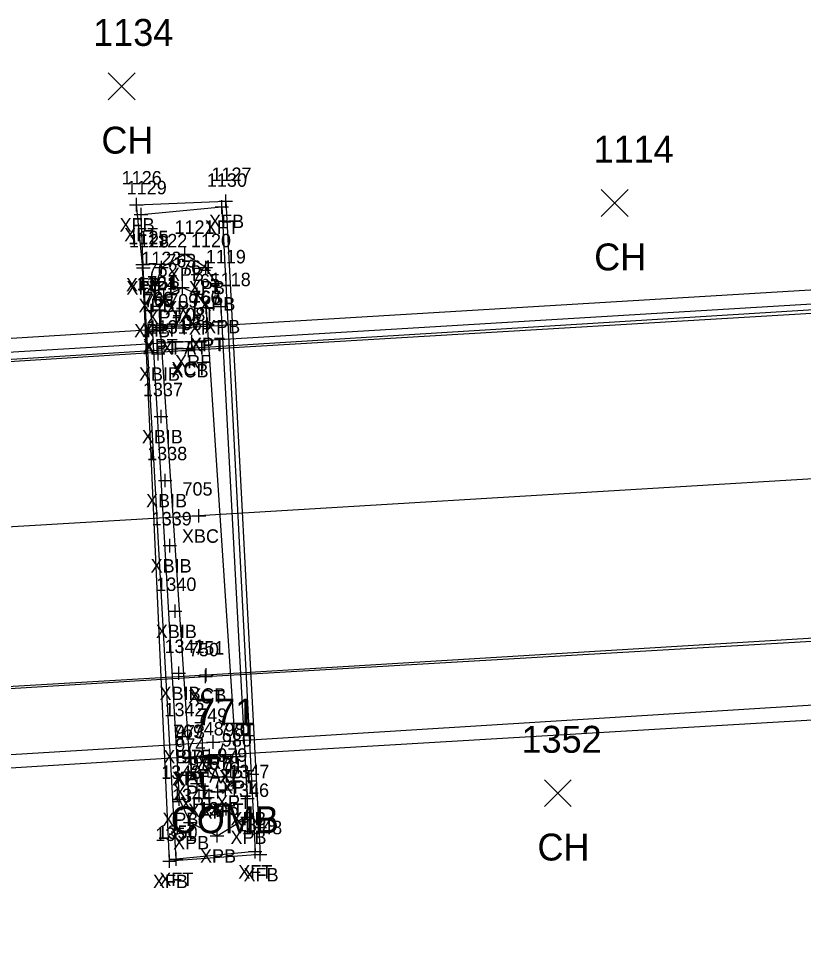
# Model space of a CAD drawing. Extents: x 1715662 to 1717487, y 887396 to 890004.
# Drawn here: x 1717104.2 to 1717162.5, y 888212.7 to 888281.6 of the extents above; entities that cross this region are included whole.
import ezdxf

# ---------------------------------------------------------------- set-up
doc = ezdxf.new("R2010")
doc.units = 0
for name, color, linetype in [('B_A', 7, 'Continuous'), ('B_I', 7, 'Continuous'), ('B_TIC', 7, 'Continuous'), ('BDC', 7, 'Continuous'), ('BELB', 7, 'Continuous'), ('BF', 7, 'Continuous'), ('BFT', 7, 'Continuous'), ('BR', 7, 'Continuous'), ('BSUBM', 7, 'Continuous'), ('L_A', 7, 'Continuous'), ('L_I', 7, 'Continuous'), ('L_TIC', 7, 'Continuous'), ('U_A', 7, 'Continuous'), ('U_I', 7, 'Continuous'), ('UP', 7, 'Continuous')]:
    doc.layers.add(name, color=color, linetype=linetype)

msp = doc.modelspace()

# ---------------------------------------------------------------- linework, layer by layer
at = {"layer": 'B_TIC'}
for p, q in [((1717112.953, 888267.77), (1717113.029, 888267.77)), ((1717119.298, 888267.599), (1717119.374, 888267.599)), ((1717119.593, 888268.03), (1717119.669, 888268.03)), ((1717113.302, 888267.041), (1717113.378, 888267.041)), ((1717116.563, 888264.1), (1717116.639, 888264.1)), ((1717113.421, 888263.334), (1717113.497, 888263.334)), ((1717113.469, 888263.093), (1717113.544, 888263.093)), ((1717114.823, 888263.1), (1717114.899, 888263.1)), ((1717118.113, 888263.11), (1717118.189, 888263.11)), ((1717114.383, 888261.78), (1717114.459, 888261.78)), ((1717116.378, 888261.612), (1717116.453, 888261.612)), ((1717118.893, 888261.91), (1717118.969, 888261.91)), ((1717114.993, 888260.931), (1717115.068, 888260.931)), ((1717117.481, 888261.13), (1717117.557, 888261.13)), ((1717118.138, 888260.129), (1717118.214, 888260.129)), ((1717119.253, 888260.22), (1717119.329, 888260.22)), ((1717114.043, 888259.92), (1717114.119, 888259.92)), ((1717114.671, 888259.963), (1717114.747, 888259.963)), ((1717114.707, 888258.8), (1717114.782, 888258.8)), ((1717114.723, 888258.654), (1717114.798, 888258.654)), ((1717116.542, 888258.636), (1717116.617, 888258.636)), ((1717118.201, 888258.895), (1717118.276, 888258.895)), ((1717118.23, 888258.881), (1717118.306, 888258.881)), ((1717117.065, 888257.612), (1717117.141, 888257.612)), ((1717114.573, 888256.694), (1717114.649, 888256.694)), ((1717116.83, 888256.946), (1717116.906, 888256.946)), ((1717116.833, 888257.088), (1717116.908, 888257.088)), ((1717114.787, 888252.047), (1717114.863, 888252.047)), ((1717115.1, 888247.294), (1717115.176, 888247.294)), ((1717117.602, 888244.664), (1717117.678, 888244.664)), ((1717115.442, 888242.454), (1717115.517, 888242.454)), ((1717115.827, 888237.586), (1717115.903, 888237.586)), ((1717116.104, 888232.979), (1717116.18, 888232.979)), ((1717118.077, 888232.734), (1717118.153, 888232.734)), ((1717118.151, 888232.862), (1717118.226, 888232.862)), ((1717116.387, 888228.279), (1717116.463, 888228.279)), ((1717118.657, 888227.867), (1717118.733, 888227.867)), ((1717116.881, 888226.664), (1717116.956, 888226.664)), ((1717117.001, 888226.634), (1717117.076, 888226.634)), ((1717118.391, 888226.857), (1717118.467, 888226.857)), ((1717120.369, 888226.798), (1717120.445, 888226.798)), ((1717120.401, 888226.793), (1717120.476, 888226.793)), ((1717117.029, 888225.645), (1717117.105, 888225.645)), ((1717120.53, 888226.027), (1717120.606, 888226.027)), ((1717120.147, 888224.902), (1717120.223, 888224.902)), ((1717117.467, 888224.792), (1717117.542, 888224.792)), ((1717118.075, 888224.298), (1717118.15, 888224.298)), ((1717118.994, 888224.182), (1717119.069, 888224.182)), ((1717119.585, 888224.316), (1717119.66, 888224.316)), ((1717116.145, 888223.627), (1717116.221, 888223.627)), ((1717121.205, 888223.683), (1717121.28, 888223.683)), ((1717121.207, 888222.295), (1717121.282, 888222.295)), ((1717116.95, 888221.897), (1717117.025, 888221.897)), ((1717118.945, 888220.911), (1717119.02, 888220.911)), ((1717121.779, 888219.728), (1717121.854, 888219.728)), ((1717122.153, 888219.52), (1717122.229, 888219.52)), ((1717115.423, 888219.02), (1717115.499, 888219.02)), ((1717115.913, 888219.18), (1717115.989, 888219.18))]:
    msp.add_line(p, q, dxfattribs=at)
for points in [[(1717112.95, 888267.27), (1717112.95, 888268.27)], [(1717119.59, 888267.53), (1717119.59, 888268.53)], [(1717112.45, 888267.77), (1717113.45, 888267.77)], [(1717118.795, 888267.599), (1717119.795, 888267.599)], [(1717119.09, 888268.03), (1717120.09, 888268.03)], [(1717119.295, 888267.099), (1717119.295, 888268.099)], [(1717112.799, 888267.041), (1717113.799, 888267.041)], [(1717113.299, 888266.541), (1717113.299, 888267.541)], [(1717116.56, 888263.6), (1717116.56, 888264.6)], [(1717113.418, 888262.834), (1717113.418, 888263.834)], [(1717113.465, 888262.593), (1717113.465, 888263.593)], [(1717114.82, 888262.6), (1717114.82, 888263.6)], [(1717116.06, 888264.1), (1717117.06, 888264.1)], [(1717118.11, 888262.61), (1717118.11, 888263.61)], [(1717112.918, 888263.334), (1717113.918, 888263.334)], [(1717112.965, 888263.093), (1717113.965, 888263.093)], [(1717114.32, 888263.1), (1717115.32, 888263.1)], [(1717117.61, 888263.11), (1717118.61, 888263.11)], [(1717114.38, 888261.28), (1717114.38, 888262.28)], [(1717116.374, 888261.112), (1717116.374, 888262.112)], [(1717118.89, 888261.41), (1717118.89, 888262.41)], [(1717113.88, 888261.78), (1717114.88, 888261.78)], [(1717114.989, 888260.431), (1717114.989, 888261.431)], [(1717115.874, 888261.612), (1717116.874, 888261.612)], [(1717117.478, 888260.63), (1717117.478, 888261.63)], [(1717118.39, 888261.91), (1717119.39, 888261.91)], [(1717114.489, 888260.931), (1717115.489, 888260.931)], [(1717116.978, 888261.13), (1717117.978, 888261.13)], [(1717119.25, 888259.72), (1717119.25, 888260.72)], [(1717114.04, 888259.42), (1717114.04, 888260.42)], [(1717114.668, 888259.463), (1717114.668, 888260.463)], [(1717117.635, 888260.129), (1717118.635, 888260.129)], [(1717118.135, 888259.629), (1717118.135, 888260.629)], [(1717118.75, 888260.22), (1717119.75, 888260.22)], [(1717113.54, 888259.92), (1717114.54, 888259.92)], [(1717114.168, 888259.963), (1717115.168, 888259.963)], [(1717114.703, 888258.3), (1717114.703, 888259.3)], [(1717118.197, 888258.395), (1717118.197, 888259.395)], [(1717118.227, 888258.381), (1717118.227, 888259.381)], [(1717114.203, 888258.8), (1717115.203, 888258.8)], [(1717114.219, 888258.654), (1717115.219, 888258.654)], [(1717114.719, 888258.154), (1717114.719, 888259.154)], [(1717116.038, 888258.636), (1717117.038, 888258.636)], [(1717116.538, 888258.136), (1717116.538, 888259.136)], [(1717117.697, 888258.895), (1717118.697, 888258.895)], [(1717117.727, 888258.881), (1717118.727, 888258.881)], [(1717117.062, 888257.112), (1717117.062, 888258.112)], [(1717116.562, 888257.612), (1717117.562, 888257.612)], [(1717116.827, 888256.446), (1717116.827, 888257.446)], [(1717116.829, 888256.588), (1717116.829, 888257.588)], [(1717114.07, 888256.694), (1717115.07, 888256.694)], [(1717114.57, 888256.194), (1717114.57, 888257.194)], [(1717116.327, 888256.946), (1717117.327, 888256.946)], [(1717116.329, 888257.088), (1717117.329, 888257.088)], [(1717114.784, 888251.547), (1717114.784, 888252.547)], [(1717114.284, 888252.047), (1717115.284, 888252.047)], [(1717115.097, 888246.794), (1717115.097, 888247.794)], [(1717114.597, 888247.294), (1717115.597, 888247.294)], [(1717117.599, 888244.164), (1717117.599, 888245.164)], [(1717117.099, 888244.664), (1717118.099, 888244.664)], [(1717115.438, 888241.954), (1717115.438, 888242.954)], [(1717114.938, 888242.454), (1717115.938, 888242.454)], [(1717115.824, 888237.086), (1717115.824, 888238.086)], [(1717115.324, 888237.586), (1717116.324, 888237.586)], [(1717116.101, 888232.479), (1717116.101, 888233.479)], [(1717118.074, 888232.234), (1717118.074, 888233.234)], [(1717118.147, 888232.362), (1717118.147, 888233.362)], [(1717115.601, 888232.979), (1717116.601, 888232.979)], [(1717117.574, 888232.734), (1717118.574, 888232.734)], [(1717117.647, 888232.862), (1717118.647, 888232.862)], [(1717116.384, 888227.779), (1717116.384, 888228.779)], [(1717118.654, 888227.367), (1717118.654, 888228.367)], [(1717115.884, 888228.279), (1717116.884, 888228.279)], [(1717118.154, 888227.867), (1717119.154, 888227.867)], [(1717116.877, 888226.164), (1717116.877, 888227.164)], [(1717116.997, 888226.134), (1717116.997, 888227.134)], [(1717118.388, 888226.357), (1717118.388, 888227.357)], [(1717120.366, 888226.298), (1717120.366, 888227.298)], [(1717120.397, 888226.293), (1717120.397, 888227.293)], [(1717116.377, 888226.664), (1717117.377, 888226.664)], [(1717116.497, 888226.634), (1717117.497, 888226.634)], [(1717117.888, 888226.857), (1717118.888, 888226.857)], [(1717119.866, 888226.798), (1717120.866, 888226.798)], [(1717119.897, 888226.793), (1717120.897, 888226.793)], [(1717120.527, 888225.527), (1717120.527, 888226.527)], [(1717116.526, 888225.645), (1717117.526, 888225.645)], [(1717117.026, 888225.145), (1717117.026, 888226.145)], [(1717120.027, 888226.027), (1717121.027, 888226.027)], [(1717117.463, 888224.292), (1717117.463, 888225.292)], [(1717119.644, 888224.902), (1717120.644, 888224.902)], [(1717120.144, 888224.402), (1717120.144, 888225.402)], [(1717116.963, 888224.792), (1717117.963, 888224.792)], [(1717117.571, 888224.298), (1717118.571, 888224.298)], [(1717118.071, 888223.798), (1717118.071, 888224.798)], [(1717118.49, 888224.182), (1717119.49, 888224.182)], [(1717118.99, 888223.682), (1717118.99, 888224.682)], [(1717119.081, 888224.316), (1717120.081, 888224.316)], [(1717119.581, 888223.816), (1717119.581, 888224.816)], [(1717121.201, 888223.183), (1717121.201, 888224.183)], [(1717115.642, 888223.627), (1717116.642, 888223.627)], [(1717116.142, 888223.127), (1717116.142, 888224.127)], [(1717120.701, 888223.683), (1717121.701, 888223.683)], [(1717121.203, 888221.795), (1717121.203, 888222.795)], [(1717116.946, 888221.397), (1717116.946, 888222.397)], [(1717120.703, 888222.295), (1717121.703, 888222.295)], [(1717116.446, 888221.897), (1717117.446, 888221.897)], [(1717118.941, 888220.411), (1717118.941, 888221.411)], [(1717118.441, 888220.911), (1717119.441, 888220.911)], [(1717121.776, 888219.228), (1717121.776, 888220.228)], [(1717115.42, 888218.52), (1717115.42, 888219.52)], [(1717115.91, 888218.68), (1717115.91, 888219.68)], [(1717121.276, 888219.728), (1717122.276, 888219.728)], [(1717121.65, 888219.52), (1717122.65, 888219.52)], [(1717122.15, 888219.02), (1717122.15, 888220.02)], [(1717114.92, 888219.02), (1717115.92, 888219.02)], [(1717115.41, 888219.18), (1717116.41, 888219.18)]]:
    msp.add_lwpolyline(points, dxfattribs=at)
at = {"layer": 'BDC'}
for points in [[(1717176.589, 888262.234), (1717176.877, 888260.812), (1717116.829, 888257.088), (1717056.7, 888253.344), (1716997.03, 888249.858), (1716936.998, 888246.313), (1716877.496, 888242.928), (1716877.301, 888244.49)], [(1717176.976, 888262.024), (1717176.866, 888260.514), (1717116.827, 888256.946), (1717056.83, 888253.148), (1716997.002, 888249.663), (1716937.062, 888246.095), (1716877.423, 888242.56)], [(1716878.985, 888212.69), (1716878.754, 888218.609), (1716938.217, 888221.984), (1716998.215, 888225.489), (1717058.321, 888229.074), (1717118.074, 888232.734), (1717177.978, 888236.214), (1717178.104, 888235.65), (1717178.633, 888230.445)], [(1716878.76, 888218.785), (1716938.254, 888222.245), (1716997.847, 888225.861), (1717058.278, 888229.335), (1717118.147, 888232.862), (1717177.913, 888236.497)]]:
    msp.add_lwpolyline(points, dxfattribs=at)
at = {"layer": 'BELB'}
msp.add_lwpolyline([(1717176.82, 888248.242), (1717117.599, 888244.664), (1717057.58, 888241.128), (1716997.658, 888237.527), (1716937.868, 888233.85), (1716878.264, 888230.514)], dxfattribs=at)
at = {"layer": 'BF'}
for points in [[(1717176.589, 888262.234), (1717116.538, 888258.636), (1717056.61, 888254.944), (1716996.925, 888251.433), (1716937.102, 888247.945), (1716877.301, 888244.49)], [(1716878.985, 888212.69), (1716938.928, 888216.097), (1716998.537, 888219.726), (1717058.79, 888223.18), (1717118.388, 888226.857), (1717178.633, 888230.445)]]:
    msp.add_lwpolyline(points, dxfattribs=at)
at = {"layer": 'BFT'}
for points in [[(1717113.418, 888263.334), (1717112.95, 888267.77), (1717119.59, 888268.03), (1717122.15, 888219.52), (1717115.42, 888219.02)], [(1717113.465, 888263.093), (1717113.299, 888267.041), (1717119.295, 888267.599), (1717121.776, 888219.728), (1717115.91, 888219.18)], [(1717115.42, 888219.02), (1717113.418, 888263.334)], [(1717115.91, 888219.18), (1717113.465, 888263.093)]]:
    msp.add_lwpolyline(points, dxfattribs=at)
at = {"layer": 'BR'}
for points in [[(1717175.997, 888261.982), (1717175.88, 888261.141), (1717117.062, 888257.612), (1717056.557, 888253.997), (1716997.021, 888250.409), (1716936.966, 888246.784), (1716878.141, 888243.386), (1716877.962, 888244.411)], [(1716879.623, 888212.902), (1716879.679, 888213.775), (1716938.703, 888217.127), (1716998.522, 888220.762), (1717058.504, 888224.208), (1717118.654, 888227.867), (1717177.581, 888231.531), (1717177.859, 888230.636)]]:
    msp.add_lwpolyline(points, dxfattribs=at)
at = {"layer": 'BSUBM'}
for points in [[(1717119.25, 888260.22), (1717118.89, 888261.91), (1717118.11, 888263.11), (1717116.56, 888264.1), (1717114.82, 888263.1), (1717114.38, 888261.78), (1717114.04, 888259.92), (1717116.142, 888223.627), (1717116.946, 888221.897), (1717118.941, 888220.911), (1717121.203, 888222.295), (1717121.201, 888223.683)], [(1717114.703, 888258.8), (1717114.668, 888259.963), (1717114.989, 888260.931), (1717116.374, 888261.612), (1717117.478, 888261.13), (1717118.135, 888260.129), (1717118.197, 888258.895)], [(1717121.201, 888223.683), (1717119.25, 888260.22)], [(1717118.197, 888258.895), (1717114.703, 888258.8)], [(1717118.227, 888258.881), (1717114.719, 888258.654), (1717116.877, 888226.664), (1717120.366, 888226.798)], [(1717120.366, 888226.798), (1717118.227, 888258.881)], [(1717116.997, 888226.634), (1717117.026, 888225.645), (1717117.463, 888224.792), (1717118.071, 888224.298), (1717118.99, 888224.182), (1717119.581, 888224.316), (1717120.144, 888224.902), (1717120.527, 888226.027), (1717120.397, 888226.793)], [(1717120.397, 888226.793), (1717116.997, 888226.634)]]:
    msp.add_lwpolyline(points, dxfattribs=at)
at = {"layer": 'L_TIC'}
for points in [[(1717110.868, 888275.562), (1717112.868, 888277.562)], [(1717112.868, 888275.562), (1717110.868, 888277.562)], [(1717147.467, 888266.891), (1717149.467, 888268.891)], [(1717149.467, 888266.891), (1717147.467, 888268.891)], [(1717143.251, 888223.071), (1717145.251, 888225.071)], [(1717145.251, 888223.071), (1717143.251, 888225.071)]]:
    msp.add_lwpolyline(points, dxfattribs=at)
at = {"layer": 'UP'}
for p, q in [((1717119.37, 888227.765), (1717119.12, 888226.932)), ((1717118.286, 888225.265), (1717118.286, 888226.932)), ((1717118.286, 888226.932), (1717119.953, 888226.932)), ((1717119.953, 888226.932), (1717119.953, 888225.265)), ((1717119.12, 888226.099), (1717119.12, 888226.099)), ((1717119.953, 888225.265), (1717118.286, 888225.265)), ((1717118.87, 888224.432), (1717119.12, 888225.265))]:
    msp.add_line(p, q, dxfattribs=at)
msp.add_circle((1717119.12, 888226.099), 0.833, dxfattribs=at)

# ---------------------------------------------------------------- texts
at = {"layer": 'B_A'}
for s, p in [('XFB', (1717118.35, 888266.03)), ('XFB', (1717111.71, 888265.77)), ('XFT', (1717118.039, 888265.599)), ('XFT', (1717112.043, 888265.041)), ('XPB', (1717115.296, 888262.1)), ('XFB', (1717112.178, 888261.334)), ('XFT', (1717112.21, 888261.093)), ('XPB', (1717113.556, 888261.1)), ('XPB', (1717116.846, 888261.11)), ('XPB', (1717113.116, 888259.78)), ('XPB', (1717117.626, 888259.91)), ('XPT', (1717115.095, 888259.612)), ('XPT', (1717116.198, 888259.13)), ('XPT', (1717113.71, 888258.931)), ('XPB', (1717112.776, 888257.92)), ('XPT', (1717113.388, 888257.963)), ('XPT', (1717116.855, 888258.129)), ('XPB', (1717117.986, 888258.22)), ('XPT', (1717113.424, 888256.8)), ('XPT', (1717113.44, 888256.654)), ('XFAT', (1717114.794, 888256.636)), ('XPT', (1717116.918, 888256.895)), ('XPT', (1717116.947, 888256.881)), ('XRF', (1717115.822, 888255.612)), ('XCT', (1717115.55, 888255.088)), ('XCB', (1717115.563, 888254.946)), ('XBIB', (1717113.141, 888254.694)), ('XBIB', (1717113.355, 888250.047)), ('XBIB', (1717113.668, 888245.294)), ('XBC', (1717116.335, 888242.664)), ('XBIB', (1717114.009, 888240.454)), ('XBIB', (1717114.395, 888235.586)), ('XBIB', (1717114.671, 888230.979)), ('XCT', (1717116.794, 888230.734)), ('XCB', (1717116.884, 888230.862)), ('XBIB', (1717114.955, 888226.279)), ('XRF', (1717117.414, 888225.867)), ('XPT', (1717115.598, 888224.664)), ('XPT', (1717115.718, 888224.634)), ('XFAT', (1717116.644, 888224.857)), ('XPT', (1717119.086, 888224.798)), ('XPT', (1717119.118, 888224.793)), ('XPT', (1717119.247, 888224.027)), ('XPT', (1717115.746, 888223.645)), ('XPT', (1717116.184, 888222.792)), ('XPT', (1717118.864, 888222.902)), ('XPT', (1717116.792, 888222.298)), ('XPT', (1717117.711, 888222.182)), ('XPT', (1717118.302, 888222.316)), ('XPB', (1717114.878, 888221.627)), ('XPB', (1717119.937, 888221.683)), ('XPB', (1717115.682, 888219.897)), ('XPB', (1717119.94, 888220.295)), ('XPB', (1717117.678, 888218.911)), ('XFT', (1717120.52, 888217.728)), ('XFB', (1717114.18, 888217.02)), ('XFT', (1717114.654, 888217.18)), ('XFB', (1717120.91, 888217.52))]:
    msp.add_text(s, height=1, dxfattribs=at).set_placement(p)
at = {"layer": 'B_I'}
for s, p in [('1127', (1717118.527, 888269.53)), ('1126', (1717111.859, 888269.27)), ('1130', (1717118.188, 888269.099)), ('1129', (1717112.232, 888268.541)), ('1121', (1717115.78, 888265.6)), ('1125', (1717112.355, 888264.834)), ('1128', (1717112.402, 888264.593)), ('1122', (1717113.757, 888264.6)), ('1120', (1717117.004, 888264.61)), ('1123', (1717113.317, 888263.28)), ('763', (1717115.17, 888263.112)), ('1119', (1717118.107, 888263.41)), ('762', (1717113.785, 888262.431)), ('764', (1717116.273, 888262.63)), ('1124', (1717112.977, 888261.42)), ('761', (1717113.746, 888261.463)), ('765', (1717116.93, 888261.629)), ('1118', (1717118.47, 888261.72)), ('766', (1717116.965, 888260.395)), ('767', (1717117.022, 888260.381)), ('760', (1717113.455, 888260.3)), ('768', (1717113.515, 888260.154)), ('709', (1717115.314, 888260.136)), ('708', (1717115.841, 888259.112)), ('706', (1717115.579, 888258.446)), ('707', (1717115.609, 888258.588)), ('1131', (1717113.79, 888258.194)), ('1337', (1717113.437, 888253.547)), ('1338', (1717113.75, 888248.794)), ('705', (1717116.378, 888246.164)), ('1339', (1717114.088, 888243.954)), ('1340', (1717114.434, 888239.086)), ('1341', (1717115.038, 888234.479)), ('750', (1717116.85, 888234.234)), ('751', (1717117.25, 888234.362)), ('1342', (1717115.037, 888229.779)), ('749', (1717117.469, 888229.367)), ('769', (1717115.668, 888228.164)), ('973', (1717115.816, 888228.134)), ('748', (1717117.207, 888228.357)), ('770', (1717119.142, 888228.298)), ('981', (1717119.5, 888228.293)), ('980', (1717119.302, 888227.527)), ('974', (1717115.845, 888227.145)), ('975', (1717116.282, 888226.292)), ('979', (1717118.959, 888226.402)), ('976', (1717116.862, 888225.798)), ('977', (1717117.809, 888225.682)), ('978', (1717118.4, 888225.816)), ('1343', (1717114.795, 888225.127)), ('1347', (1717119.855, 888225.183)), ('1344', (1717115.6, 888223.397)), ('1346', (1717119.829, 888223.795)), ('1345', (1717117.595, 888222.411)), ('1349', (1717120.425, 888221.228)), ('1351', (1717114.357, 888220.52)), ('1350', (1717114.52, 888220.68)), ('1348', (1717120.804, 888221.02))]:
    msp.add_text(s, height=1, dxfattribs=at).set_placement(p)
at = {"layer": 'L_A'}
for p in [(1717110.356, 888271.562), (1717146.955, 888262.891), (1717142.739, 888219.071)]:
    msp.add_text('CH', height=2, dxfattribs=at).set_placement(p)
at = {"layer": 'L_I'}
for s, p in [('1134', (1717109.742, 888279.562)), ('1114', (1717146.908, 888270.891)), ('1352', (1717141.558, 888227.071))]:
    msp.add_text(s, height=2, dxfattribs=at).set_placement(p)
at = {"layer": 'U_A'}
msp.add_text('COMB', height=2, dxfattribs=at).set_placement((1717115.506, 888221.099))
at = {"layer": 'U_I'}
msp.add_text('771', height=2, dxfattribs=at).set_placement((1717117.324, 888229.099))

doc.saveas('drawing.dxf')
